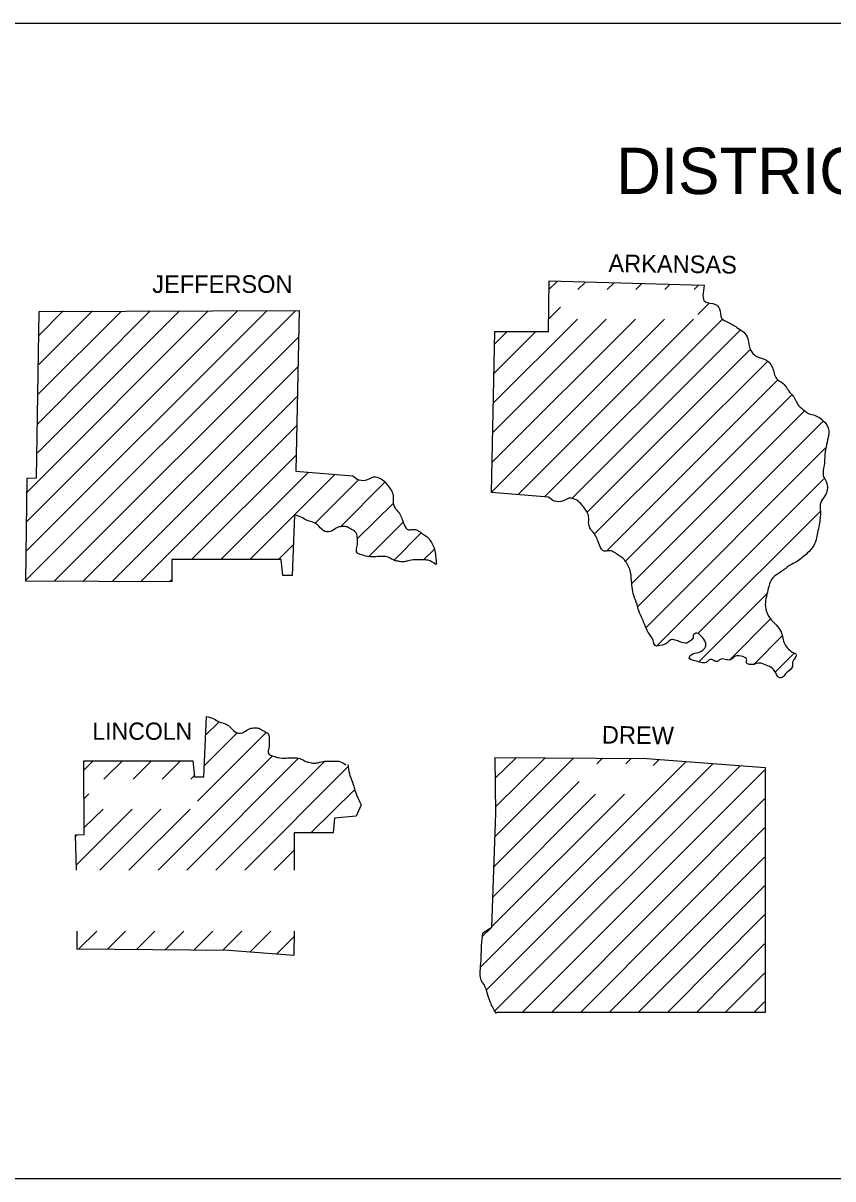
# Model space of a CAD drawing. Extents: x 76 to 6945, y -3933 to 2152.
# Drawn here: x 6504 to 6701.5, y -1611 to -1329.1 of the extents above; entities that cross this region are included whole.
import ezdxf

# ---------------------------------------------------------------- set-up
doc = ezdxf.new("R2010")
doc.units = 0
doc.layers.add('R_Draft', color=7, linetype='Continuous')

msp = doc.modelspace()

# ---------------------------------------------------------------- linework, layer by layer
at = {"layer": 'R_Draft'}
msp.add_lwpolyline([(6898.43, -1610.95), (6492.33, -1610.95), (6492.33, -1329.05), (6898.43, -1329.05)], close=True, dxfattribs=at)
for points in [[(6619.03, -1404.25), (6632.13, -1404.25), (6632.33, -1391.95), (6670.13, -1392.95)], [(6632.23, -1394.05), (6634.23, -1392.05)], [(6639.33, -1394.05), (6641.13, -1392.25)], [(6646.43, -1394.05), (6648.03, -1392.45)], [(6653.43, -1394.05), (6654.93, -1392.55)], [(6660.53, -1394.05), (6661.83, -1392.75)], [(6667.63, -1394.05), (6668.73, -1392.95)], [(6668.53, -1400.15), (6671.23, -1397.45)], [(6504.73, -1465.15), (6505.03, -1440.05), (6507.33, -1439.95), (6507.93, -1399.35), (6571.33, -1399.15)], [(6504.73, -1464.95), (6570.43, -1399.25)], [(6504.83, -1457.75), (6563.43, -1399.25)], [(6504.93, -1450.65), (6556.33, -1399.25)], [(6505.03, -1443.45), (6549.13, -1399.25)], [(6507.53, -1433.85), (6542.13, -1399.25)], [(6507.63, -1426.75), (6535.03, -1399.25)], [(6507.73, -1419.55), (6527.93, -1399.35)], [(6507.83, -1412.35), (6520.93, -1399.25)], [(6507.83, -1405.25), (6513.83, -1399.25)], [(6571.33, -1399.15), (6570.53, -1438.35), (6584.43, -1439.45)], [(6632.13, -1401.25), (6635.03, -1398.35)], [(6618.33, -1443.35), (6660.43, -1401.25)], [(6618.43, -1436.15), (6653.33, -1401.25)], [(6618.63, -1428.85), (6646.23, -1401.25)], [(6618.73, -1421.65), (6639.23, -1401.25)], [(6624.73, -1444.05), (6667.53, -1401.25)], [(6631.23, -1444.55), (6674.53, -1401.25)], [(6511.63, -1465.15), (6571.23, -1405.55)], [(6632.13, -1444.65), (6618.23, -1443.55), (6619.03, -1404.25)], [(6618.93, -1414.45), (6629.03, -1404.25)], [(6619.03, -1407.25), (6622.03, -1404.25)], [(6637.93, -1444.95), (6678.83, -1404.05)], [(6641.63, -1448.25), (6681.33, -1408.65)], [(6643.43, -1453.55), (6685.53, -1411.55)], [(6518.63, -1465.25), (6571.03, -1412.85)], [(6646.33, -1457.75), (6688.03, -1416.05)], [(6525.73, -1465.25), (6570.93, -1420.05)], [(6650.93, -1460.25), (6691.43, -1419.75)], [(6652.43, -1465.75), (6694.63, -1423.55)], [(6653.93, -1471.35), (6699.23, -1426.05)], [(6532.73, -1465.25), (6570.73, -1427.25)], [(6545.13, -1459.85), (6570.63, -1434.45)], [(6655.93, -1476.45), (6699.63, -1432.75)], [(6552.23, -1459.85), (6573.53, -1438.65)], [(6559.33, -1459.85), (6580.03, -1439.15)], [(6575.23, -1451.05), (6585.83, -1440.45)], [(6658.53, -1480.95), (6699.23, -1440.25)], [(6581.43, -1451.95), (6592.23, -1441.05)], [(6585.43, -1454.95), (6594.33, -1446.15)], [(6668.63, -1477.85), (6698.43, -1448.05)], [(6570.23, -1449.05), (6569.63, -1463.75), (6567.33, -1463.75), (6566.93, -1459.85), (6540.33, -1459.85), (6540.33, -1465.35)], [(6588.23, -1459.25), (6596.63, -1450.85)], [(6594.43, -1460.15), (6601.13, -1453.35)], [(6566.33, -1459.85), (6569.93, -1456.25)], [(6601.63, -1459.95), (6604.23, -1457.45)], [(6540.13, -1465.35), (6504.73, -1465.15)], [(6539.73, -1465.25), (6540.33, -1464.75)], [(6668.93, -1484.65), (6685.53, -1468.05)], [(6676.33, -1484.35), (6686.33, -1474.25)], [(6666.83, -1479.65), (6667.13, -1479.35), (6667.43, -1479.05), (6667.43, -1479.05)], [(6682.23, -1485.45), (6689.23, -1478.45)], [(6687.43, -1487.35), (6692.03, -1482.75)], [(6517.03, -1535.65), (6516.83, -1527.05), (6518.93, -1526.95), (6518.83, -1508.95), (6545.43, -1508.95), (6545.83, -1512.85), (6548.13, -1512.85), (6548.73, -1498.15)], [(6548.53, -1502.75), (6551.83, -1499.45)], [(6546.53, -1518.85), (6563.33, -1502.05)], [(6548.13, -1510.25), (6556.13, -1502.25)], [(6536.93, -1535.65), (6564.83, -1507.75)], [(6619.03, -1508.15), (6656.13, -1508.45), (6684.93, -1510.65)], [(6619.33, -1521.75), (6619.13, -1508.15)], [(6518.93, -1511.15), (6521.13, -1508.95)], [(6523.73, -1513.45), (6528.23, -1508.95)], [(6530.83, -1513.45), (6535.23, -1509.05)], [(6537.93, -1513.45), (6542.33, -1509.05)], [(6543.93, -1535.65), (6571.13, -1508.45)], [(6551.03, -1535.65), (6577.63, -1509.05)], [(6558.13, -1535.65), (6583.23, -1510.45)], [(6615.63, -1559.25), (6665.63, -1509.25)], [(6617.03, -1564.85), (6672.23, -1509.75)], [(6619.13, -1569.85), (6678.83, -1510.25)], [(6619.23, -1513.15), (6624.23, -1508.25)], [(6619.23, -1527.35), (6638.23, -1508.35)], [(6619.33, -1520.15), (6631.23, -1508.35)], [(6643.93, -1509.75), (6645.33, -1508.35)], [(6651.03, -1509.75), (6652.33, -1508.45)], [(6657.63, -1510.15), (6659.03, -1508.75)], [(6684.93, -1510.65), (6684.93, -1570.35)], [(6544.93, -1513.45), (6545.73, -1512.65)], [(6625.73, -1570.35), (6684.83, -1511.25)], [(6574.23, -1526.55), (6584.83, -1516.05)], [(6618.93, -1534.75), (6639.63, -1514.05)], [(6518.93, -1518.15), (6520.03, -1517.05)], [(6618.43, -1549.35), (6650.63, -1517.15)], [(6618.63, -1542.15), (6643.63, -1517.15)], [(6632.83, -1570.35), (6684.83, -1518.25)], [(6517.03, -1534.35), (6530.63, -1520.75)], [(6518.93, -1525.25), (6523.53, -1520.75)], [(6522.73, -1535.65), (6537.63, -1520.75)], [(6529.83, -1535.65), (6544.73, -1520.75)], [(6586.43, -1519.75), (6585.23, -1522.45), (6579.93, -1522.95), (6579.63, -1526.55), (6570.13, -1526.55), (6570.13, -1535.65)], [(6616.13, -1550.95), (6618.33, -1549.55), (6619.33, -1521.75)], [(6516.93, -1527.35), (6517.23, -1527.05)], [(6639.93, -1570.35), (6684.83, -1525.35)], [(6565.23, -1535.65), (6570.13, -1530.75)], [(6646.93, -1570.35), (6684.83, -1532.45)], [(6654.03, -1570.35), (6684.83, -1539.45)], [(6661.13, -1570.35), (6684.83, -1546.55)], [(6616.03, -1551.75), (6618.03, -1549.85)], [(6517.23, -1554.95), (6517.23, -1550.55)], [(6517.53, -1554.95), (6522.03, -1550.55)], [(6524.63, -1554.95), (6529.03, -1550.55)], [(6531.63, -1555.05), (6536.13, -1550.55)], [(6538.63, -1555.15), (6543.23, -1550.55)], [(6545.63, -1555.15), (6550.33, -1550.55)], [(6552.73, -1555.15), (6557.33, -1550.55)], [(6559.33, -1555.65), (6564.43, -1550.55)], [(6565.93, -1556.05), (6570.13, -1551.85)], [(6570.13, -1550.55), (6570.03, -1556.45)], [(6570.03, -1556.45), (6554.23, -1555.25), (6517.13, -1554.95)], [(6668.23, -1570.35), (6684.83, -1553.65)], [(6675.23, -1570.35), (6684.83, -1560.75)], [(6682.23, -1570.35), (6684.83, -1567.75)], [(6684.93, -1570.35), (6619.43, -1570.35)]]:
    msp.add_lwpolyline(points, dxfattribs=at)
for points in [[(6670.13, -1392.95), (6670.43, -1397.05), (6672.83, -1397.65), (6673.83, -1398.75), (6674.33, -1401.05), (6676.03, -1402.05), (6678.33, -1403.45), (6679.73, -1404.45), (6680.73, -1406.05), (6681.33, -1408.65), (6682.93, -1410.35), (6685.13, -1411.15), (6686.73, -1413.05), (6687.73, -1415.75), (6689.33, -1416.95), (6690.93, -1419.05), (6691.73, -1419.95), (6693.13, -1422.35), (6694.53, -1423.55), (6695.53, -1424.25), (6697.13, -1424.75), (6699.13, -1426.05), (6700.43, -1428.05), (6700.43, -1429.55), (6699.93, -1431.85), (6699.53, -1434.25), (6699.33, -1436.95), (6699.13, -1439.35), (6700.03, -1441.35), (6699.53, -1444.35), (6698.53, -1445.95), (6698.43, -1448.15), (6698.13, -1451.45), (6697.73, -1453.35), (6696.83, -1456.45), (6695.23, -1458.35)], [(6584.43, -1439.45), (6585.93, -1440.45), (6588.03, -1440.35), (6589.43, -1439.75), (6590.53, -1439.85), (6592.03, -1440.75), (6593.03, -1441.95), (6593.73, -1442.85), (6594.23, -1444.25), (6594.23, -1445.55), (6594.73, -1447.35), (6595.33, -1448.05), (6596.13, -1449.35), (6596.63, -1450.55), (6596.93, -1451.35), (6598.03, -1452.65), (6599.03, -1452.55), (6599.93, -1452.65), (6601.13, -1453.35), (6602.93, -1454.75), (6603.23, -1455.15), (6604.43, -1457.75), (6604.63, -1459.35), (6604.83, -1460.95)], [(6692.53, -1483.25), (6692.03, -1484.25), (6691.63, -1484.95), (6691.63, -1485.95), (6690.13, -1487.55), (6689.43, -1488.45), (6688.53, -1488.75), (6687.53, -1487.55), (6686.73, -1486.45), (6685.23, -1485.65), (6683.53, -1485.15), (6682.23, -1485.45), (6680.43, -1485.05), (6680.43, -1484.15), (6679.73, -1483.65), (6677.53, -1483.55), (6676.43, -1484.35), (6674.03, -1484.25), (6673.33, -1484.75), (6671.53, -1484.25), (6670.83, -1484.85), (6668.13, -1484.65), (6666.43, -1483.85), (6666.93, -1483.15), (6668.73, -1482.55), (6670.03, -1481.75), (6670.43, -1481.15), (6670.43, -1480.15), (6669.33, -1478.55), (6668.33, -1477.85), (6667.43, -1478.35), (6667.33, -1479.25), (6666.83, -1479.65), (6665.83, -1480.25), (6664.23, -1479.95), (6663.03, -1479.55), (6661.93, -1479.45), (6661.03, -1480.25), (6659.83, -1480.75), (6658.13, -1480.85), (6657.63, -1479.65), (6656.43, -1477.65), (6655.63, -1475.85), (6655.03, -1474.45), (6654.13, -1472.35), (6653.73, -1470.85), (6652.93, -1468.65), (6652.53, -1466.65), (6652.33, -1464.55), (6652.13, -1462.95), (6650.93, -1460.35), (6650.63, -1459.95), (6648.83, -1458.55), (6647.63, -1457.85), (6646.73, -1457.75), (6645.73, -1457.85), (6644.63, -1456.55), (6644.33, -1455.75), (6643.83, -1454.55), (6643.03, -1453.25), (6642.43, -1452.55), (6641.93, -1450.75), (6641.93, -1449.45), (6641.43, -1448.05), (6640.73, -1447.15), (6639.73, -1445.95), (6638.23, -1445.05), (6637.13, -1444.95), (6635.73, -1445.55), (6633.63, -1445.65), (6632.13, -1444.65)], [(6604.73, -1461.15), (6602.73, -1460.05), (6601.73, -1459.95), (6600.13, -1459.95), (6599.13, -1459.95), (6597.43, -1460.35), (6596.43, -1460.45), (6595.23, -1460.25), (6594.43, -1460.05), (6593.33, -1459.45), (6592.03, -1459.15), (6590.43, -1459.15), (6588.73, -1459.25), (6586.23, -1458.65), (6585.53, -1458.35), (6585.53, -1456.25), (6585.53, -1454.75), (6585.33, -1453.45), (6584.13, -1452.55), (6583.03, -1451.95), (6582.03, -1451.85), (6580.73, -1452.05), (6579.43, -1452.85), (6577.63, -1453.05), (6576.13, -1451.75), (6575.03, -1450.95), (6573.33, -1450.35), (6572.03, -1449.65), (6570.23, -1449.05)], [(6695.23, -1458.35), (6692.73, -1460.35), (6690.93, -1461.35), (6689.03, -1462.75), (6686.73, -1464.45), (6685.63, -1467.35), (6685.03, -1471.35), (6685.83, -1473.75), (6687.63, -1475.85), (6688.83, -1477.55), (6689.73, -1480.55), (6691.93, -1482.65), (6692.63, -1482.95)], [(6548.73, -1498.15), (6550.53, -1498.75), (6551.83, -1499.45), (6553.53, -1500.05), (6554.63, -1500.85), (6556.13, -1502.15), (6557.93, -1501.95), (6559.23, -1501.15), (6560.53, -1500.95), (6561.53, -1501.05), (6562.63, -1501.65), (6563.83, -1502.55), (6564.03, -1503.85), (6564.03, -1505.35), (6564.03, -1507.45), (6564.73, -1507.75), (6567.23, -1508.35), (6568.93, -1508.25), (6570.53, -1508.25), (6571.83, -1508.55), (6572.93, -1509.15), (6573.73, -1509.35), (6574.93, -1509.55), (6575.93, -1509.45), (6577.63, -1509.05), (6578.63, -1509.05), (6580.23, -1509.05), (6581.23, -1509.15), (6582.73, -1509.95)], [(6583.23, -1509.85), (6583.33, -1510.55), (6583.73, -1512.55), (6584.53, -1514.75), (6584.93, -1516.25), (6585.83, -1518.35), (6586.43, -1519.75)], [(6619.43, -1570.65), (6618.13, -1568.25), (6617.43, -1566.35), (6616.73, -1564.15), (6615.53, -1561.85), (6615.53, -1559.75), (6615.73, -1556.95), (6615.83, -1554.05), (6616.13, -1550.95)]]:
    msp.add_spline(points, degree=3, dxfattribs=at)

# ---------------------------------------------------------------- texts
for s, height, p in [('DISTRICT 2', 11.3, (6648.63, -1370.75)), ('JEFFERSON', 4.3, (6535.53, -1394.85)), ('LINCOLN', 4.2, (6520.93, -1503.85))]:
    msp.add_text(s, height=height, dxfattribs=at).set_placement(p)
for s, rotation, p in [('ARKANSAS', 359.2678, (6646.73, -1389.75)), ('DREW', 359.2258, (6645.13, -1504.75))]:
    msp.add_text(s, height=4.3, rotation=rotation, dxfattribs=at).set_placement(p)

doc.saveas('drawing.dxf')
